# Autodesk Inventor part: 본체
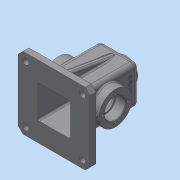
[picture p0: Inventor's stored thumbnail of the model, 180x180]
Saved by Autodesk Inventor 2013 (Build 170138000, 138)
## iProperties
Created: 2018-10
Part Number: 본체
Material: 일반
Document SubType Name: Modeling
Designer: Administrator
Density: 1 g/cm^3
Author: Administrator
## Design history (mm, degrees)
sketch "스케치1"
  geometry: L1 (-32.5, 110)-(32.5, 110); L2 (32.5, 110)-(32.5, 0); L3 (32.5, 0)-(-32.5, 0); L4 (-32.5, 0)-(-32.5, 110); 2 further points
  constraints: 8 end point, 2 parallel, 1 coincident, 1 horizontal, 1 midpoint, 1 perpendicular
  dimensions: "d0" = 65 distance of L1.start L1.end; "d2" = 110 distance of L1.end L2.end
extrude "돌출1" new body sketch "스케치1" stored distance "d3" = 65; taper "d4" = 0 deg
feature "쉘1" dims "d5" = 5
sketch "스케치2"
  geometry: L1 (65, 0)-(65, -65) reference; L2 (-27.5, -92.5)-(92.5, -92.5); L3 (92.5, -92.5)-(92.5, 27.5); L4 (92.5, 27.5)-(-27.5, 27.5); L5 (-27.5, 27.5)-(-27.5, -92.5); L6 (-27.5, -92.5)-(92.5, 27.5); L7 (92.5, -92.5)-(-27.5, 27.5); L8 (5, -60)-(60, -60) reference; L9 (60, -60)-(60, -5) reference; L10 (60, -5)-(5, -5) reference; L11 (5, -5)-(5, -60) reference; L12 (65, -65)-(0, -65) reference; L13 (0, -65)-(0, 0) reference; L14 (0, 0)-(65, 0) reference; L15 (65, 0)-(65, -65) reference; 1 further point
  constraints: 12 end point, 2 midpoint, 2 parallel, 1 horizontal, 1 perpendicular
  dimensions: "d6" = 120 distance of L3.end L4.end; "d8" = 120 distance of L2.end L3.end
extrude "돌출2" join sketch "스케치2" distance "d9" = 10; taper "d10" = 0 deg
chamfer "모따기1" distance "d11" = 8; stored, may be unused: second distance "d12" = 2, angle "d13" = 45 deg
sketch "스케치3"
  geometry: C1 r 5 at (-15, 80); 1 further point
  constraints: 1 centre point
  dimensions: "d16" = 10 diameter of C1; "d18" = 47.5 horizontal distance of point (32.5, 32.5) C1.centre; "d19" = 47.5 horizontal distance of point (32.5, 32.5) C1.centre
extrude "돌출3" cut sketch "스케치3" stored distance "d20" = 10; taper "d21" = 0 deg
fillet "모깎기1" dims "d22" = 8
fillet "모깎기2" dims "d23" = 8
sketch "스케치5"
  geometry: L1 (84.5, -10)-(-35.5, -10) reference; L2 (-35.5, -10)-(-35.5, 0) reference; L3 (-35.5, 0)-(0, 0) reference; L4 (0, 0)-(0, 92) reference; L5 (0, 92)-(49, 92) reference; L6 (49, 92)-(49, 0) reference; L7 (0, 0)-(49, 0) reference; L8 (84.5, 0)-(84.5, -10) reference; L9 (49, 0)-(84.5, 0) reference; L10 (76.5, -10)-(-27.5, -10) reference; L11 (84.5, -10)-(-35.5, -10) reference; L12 (-35.5, -10)-(-35.5, 0) reference; L13 (-35.5, 0)-(0, 0) reference; L14 (0, 0)-(0, 92) reference; L15 (0, 92)-(49, 92) reference; L16 (49, 92)-(49, 0) reference; L17 (0, 0)-(49, 0) reference; L18 (84.5, 0)-(84.5, -10) reference; L19 (49, 0)-(84.5, 0) reference; L20 (84.5, -10)-(-35.5, -10) reference; L21 (-35.5, -10)-(-35.5, 0) reference; L22 (-35.5, 0)-(0, 0) reference; L23 (0, 0)-(0, 92) reference; L24 (0, 92)-(49, 92) reference; L25 (49, 92)-(49, 0) reference; L26 (0, 0)-(49, 0) reference; L27 (84.5, 0)-(84.5, -10) reference; L28 (49, 0)-(84.5, 0) reference; C1 r 27.5 at (24.5, 45); 2 further points
  constraints: 1 centre point, 1 midpoint, 1 vertical alignment
  dimensions: "d37" = 55 diameter of C1; "d39" = 55 distance from line of L1 C1.centre
extrude "돌출5" join sketch "스케치5" distance "d40" = 15; taper "d41" = 0 deg
sketch "스케치6"
  geometry: C1 r 27.5 at (0, 0) reference; C2 r 15 at (0, 0); 1 further point
  constraints: 1 centre point, 1 coincident
  dimensions: "d44" = 30 diameter of C2
extrude "돌출6" cut sketch "스케치6" stored distance "d45" = 15; taper "d46" = 0 deg
sketch "스케치7"
  geometry: C1 r 15 at (0, 0) reference; C2 r 27.5 at (0, 0) reference; C3 r 17.5 at (0, 0); 1 further point
  constraints: 1 centre point, 1 coincident
  dimensions: "d47" = 35 diameter of C3
extrude "돌출7" cut sketch "스케치7" distance "d48" = 17; taper "d49" = 0 deg
chamfer "모따기2" distance "d50" = 1; stored, may be unused: second distance "d51" = 2, angle "d52" = 45 deg
fillet "모깎기14" dims "d89" = 3
sketch "스케치8"
  geometry: C1 r 27.5 at (0, 0) reference; 2 further points
  constraints: 1 vertical alignment
  dimensions: "d53" = 21 distance of C1.centre point (0, 21)
hole "구멍2" sketch "스케치8" at (0, 21) diameter "d54" = 3.459; stored, may be unused: countersink angle "d58" = 90 deg, drill point angle "d60" = 118 deg; dims "d55" = 8, "d56" = 4, "d57" = 2, "d59" = 10
sketch "스케치9"
  geometry: L1 (27.312, 45.132)-(11.044, 48); L2 (10, 60)-(0, 60) reference; 1 further point
  constraints: 2 end point
  dimensions: "d64" = 10 deg angle of L2 L1; "d65" = 12 distance from line of L2 L1.end
feature "리브1" sketch "스케치9" dims "d66" = 1, "d67" = 10, "d68" = 0, "d69" = 0, "d70" = 1, "d71" = 1
fillet "모깎기15" dims "d90" = 3
fillet "모깎기4" dims "d72" = 3
fillet "모깎기5" dims "d73" = 3
fillet "모깎기6" dims "d74" = 3
fillet "모깎기7" dims "d75" = 3
sketch "스케치10"
  geometry: L1 (-42.5, 21.823)-(-42.5, 12.093); L2 (-27.5, 105)-(-27.5, 0) reference; 1 further point
  constraints: 2 end point, 1 vertical
  dimensions: "d76" = 15 distance between parallel lines of L2 L1
feature "리브2" sketch "스케치10" dims "d77" = 1, "d78" = 6, "d79" = 0, "d80" = 0, "d81" = 1, "d82" = 1
fillet "모깎기8" dims "d83" = 3
fillet "모깎기9" dims "d84" = 3
fillet "모깎기10" dims "d85" = 1
fillet "모깎기11" dims "d86" = 0.3
fillet "모깎기12" dims "d87" = 3
fillet "모깎기13" dims "d88" = 3
sketch "스케치11"
  geometry: L1 (5.728, 18)-(43.272, 18) reference; L2 (-8, 0)-(-8, -91) reference; 2 further points
  constraints: 1 other
  dimensions: "d91" = 26 distance from line of point (24.5, -8) L1; "d92" = 32.5 distance from line of point (24.5, -8) L2
feature "엠보싱1" sketch "스케치11" dims "d6" = 120, "d8" = 120, "d93" = 0.5, "d94" = 0
fillet "모깎기16" dims "d95" = 3
fillet "모깎기17" dims "d96" = 3
node "작업 평면1"
sketch "스케치12"
  geometry: C1 r 20 at (24.5, 24.5); 1 further point
  constraints: 1 centre point, 1 coincident
  dimensions: "d98" = 40 diameter of C1
extrude "돌출8" join sketch "스케치12" stored distance "d99" = 17; taper "d100" = 7 deg
hole "구멍3" diameter "d103" = 22.835; stored, may be unused: countersink angle "d107" = 90 deg, drill point angle "d109" = 0 deg; dims "d101" = 10, "d102" = 10, "d104" = 25, "d105" = 4, "d106" = 2, "d108" = 30
fillet "모깎기18" dims "d110" = 3
chamfer "모따기3" distance "d111" = 1; stored, may be unused: second distance "d112" = 2, angle "d113" = 45 deg
node "솔리드1"
mirror "대칭1"
mirror "대칭2"
pattern_circular "원형 패턴1" dims angle "d62" = 360 deg
mirror "대칭3"
mirror "대칭4"
mirror "대칭5"
node "절단 모서리 투영1"
node "절단 모서리 투영2"
node "절단 모서리 투영3"
node "절단 모서리 투영4"
